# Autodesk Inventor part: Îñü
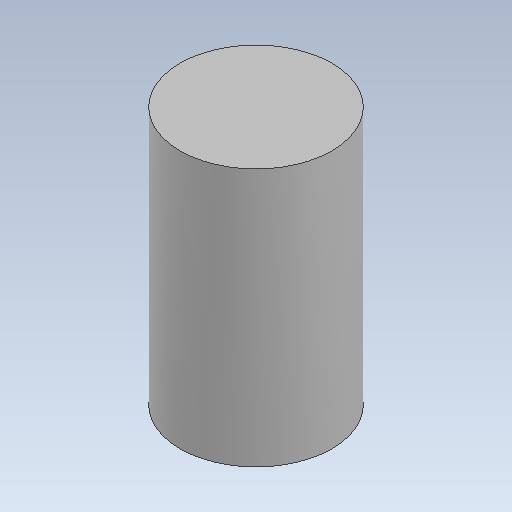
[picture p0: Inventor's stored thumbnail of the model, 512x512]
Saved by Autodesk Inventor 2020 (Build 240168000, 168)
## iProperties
Created: 1900-01
Part Number: Îñü
Material: Générique
Document SubType Name: Modeling
Designer: bruno
Density: 1 g/cm^3
Appearance: Par défaut
Author: bruno
Revision Number: ANYUNSPECIFIED
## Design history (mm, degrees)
feature "Base1"
node "Solide1"
